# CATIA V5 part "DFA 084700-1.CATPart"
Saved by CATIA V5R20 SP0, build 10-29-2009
Part number: DFA 084700-1
Revision: ANY
Definition: UNKNOWN
Nomenclature: DFA 084700-1
Source: Unknown
Bounding box of the stored display mesh (mm): x -2.853 to 2.853, y 0.2 to 2.5, z -3 to 3
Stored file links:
  C:\Users\Utente\Desktop\IO LAVORO\3D X SITO CF\CUMSA\3D files FA\FA 084705-21\DFA 084700-1.CATPart
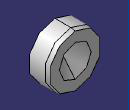
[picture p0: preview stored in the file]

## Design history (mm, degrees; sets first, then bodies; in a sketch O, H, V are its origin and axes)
Body1 "Cortar-Extruir1" (main body)
  Solid1: solid without history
